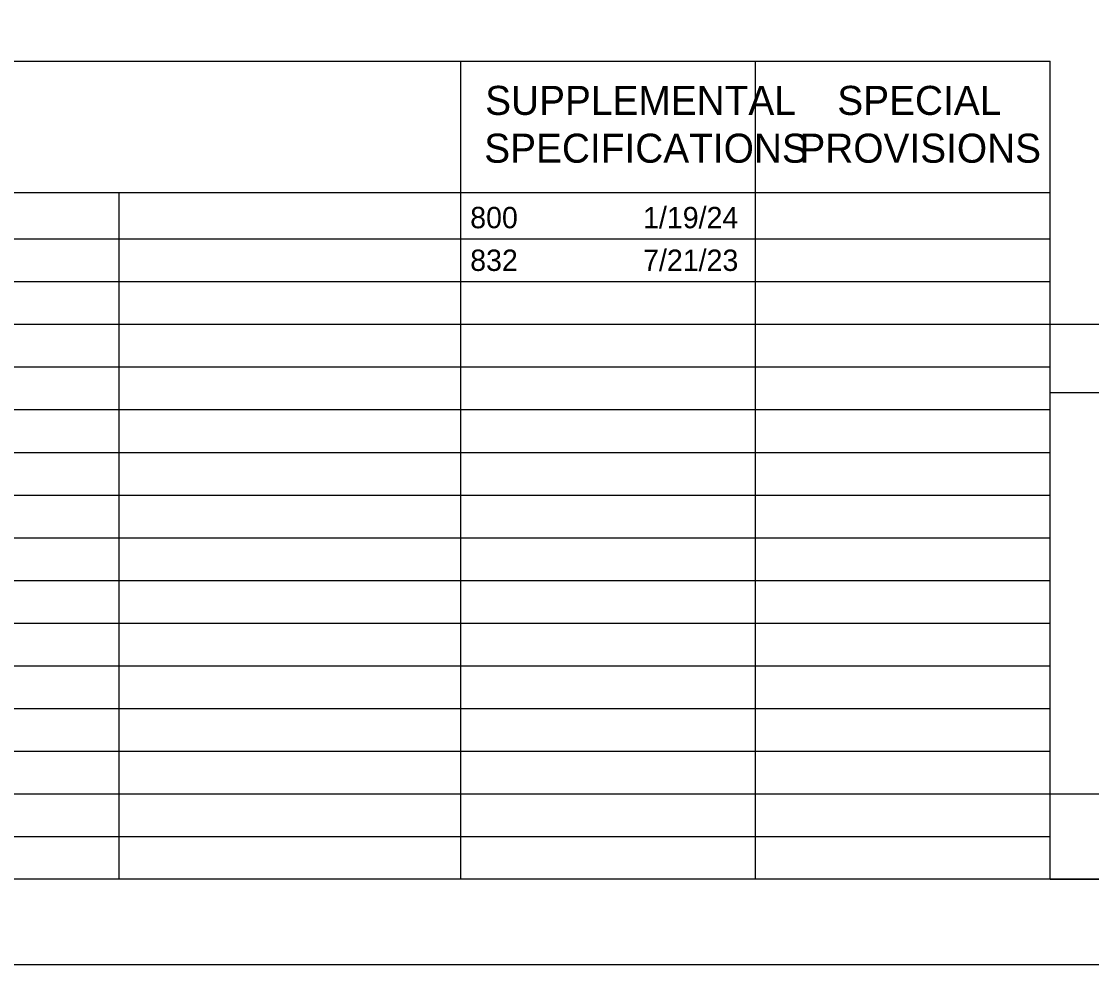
# Model space of a CAD drawing. Extents: x -8 to 42.1, y -22 to 0.
# Drawn here: x 17.58 to 23.84, y -22 to -16.48 of the extents above; entities that cross this region are included whole.
import ezdxf

# ---------------------------------------------------------------- set-up
doc = ezdxf.new("R2010")
doc.units = 0
for name, color, linetype in [('SH_Border', 7, 'Continuous'), ('SH_Cut_Line', 7, 'Continuous'), ('SH_Data', 7, 'Continuous'), ('SH_Text', 7, 'Continuous')]:
    doc.layers.add(name, color=color, linetype=linetype)

msp = doc.modelspace()

# ---------------------------------------------------------------- linework, layer by layer
at = {"layer": 'SH_Border'}
msp.add_lwpolyline([(1.5, -0.5), (33.5, -0.5), (33.5, -21.5), (1.5, -21.5)], close=True, dxfattribs=at)
at = {"layer": 'SH_Cut_Line'}
msp.add_lwpolyline([(0, -22), (34, -22), (34, 0), (0, 0)], close=True, dxfattribs=at)
at = {"layer": 'SH_Data'}
for p, q in [((10.15, -16.7082), (23.6, -16.7082)), ((20.15, -21.5), (20.15, -16.7082)), ((21.875, -21.5), (21.875, -16.7082)), ((23.6, -21.5), (23.6, -16.7082)), ((10.15, -17.4791), (23.6, -17.4791)), ((18.15, -21.5), (18.15, -17.4791)), ((10.15, -17.75), (23.6, -17.75)), ((10.15, -18), (23.6, -18)), ((10.15, -18.25), (23.6, -18.25)), ((23.6, -21.5), (23.6, -18.25)), ((23.6, -21.5), (23.6, -18.25)), ((23.6, -18.25), (26.4, -18.25)), ((10.15, -18.5), (23.6, -18.5)), ((23.6, -18.65), (26.4, -18.65)), ((10.15, -18.75), (23.6, -18.75)), ((10.15, -19), (23.6, -19)), ((10.15, -19.25), (23.6, -19.25)), ((10.15, -19.5), (23.6, -19.5)), ((10.15, -19.75), (23.6, -19.75)), ((10.15, -20), (23.6, -20)), ((10.15, -20.25), (23.6, -20.25)), ((10.15, -20.5), (23.6, -20.5)), ((10.15, -20.75), (23.6, -20.75)), ((10.15, -21), (23.6, -21)), ((10.15, -21.25), (23.6, -21.25)), ((23.6, -21.5), (26.4, -21.5)), ((23.6, -21.5), (26.4, -21.5))]:
    msp.add_line(p, q, dxfattribs=at)
msp.add_lwpolyline([(23.6, -21.5), (23.6, -21), (26.4, -21), (26.4, -21.5)], close=True, dxfattribs=at)

# ---------------------------------------------------------------- texts
at = {"layer": 'SH_Text'}
for s, height, p in [('SUPPLEMENTAL', 0.17, (20.2925, -17.0237)), ('SPECIAL', 0.17, (22.3542, -17.0237)), ('SPECIFICATIONS', 0.17, (20.2871, -17.3037)), ('PROVISIONS', 0.17, (22.1323, -17.3037)), ('800', 0.125, (20.205, -17.6875)), ('1/19/24', 0.125, (21.2171, -17.6875)), ('832', 0.125, (20.205, -17.9375)), ('7/21/23', 0.125, (21.2171, -17.9375))]:
    msp.add_text(s, height=height, dxfattribs=at).set_placement(p)

doc.saveas('drawing.dxf')
